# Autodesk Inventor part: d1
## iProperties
Created: 2002-02
Part Number: d1
Document SubType Name: ﾓﾃﾞﾘﾝｸﾞ
Designer: Administrator
Control State: 0
Master: False
Checked Out: False
Shininess: 64.0
Length Units: 11269
Angle Units: 11279
Time Units: 11290
Mass Units: 11284
Length Display Precision: 2
Angle Display Precision: 1
Density: 0.0
Volumn: 0.0
Area: 0.0
PropertySet Name: Model Information
Author: Administrator
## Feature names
1. 押し出し3 [Extrusion]
